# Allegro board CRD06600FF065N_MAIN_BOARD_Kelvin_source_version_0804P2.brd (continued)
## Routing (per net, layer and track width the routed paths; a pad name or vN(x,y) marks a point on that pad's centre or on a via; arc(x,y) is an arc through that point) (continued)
N17288650: length 5.7
  BOTTOM w0.508: R68.1 C36.1 R250.2 83.19,110.62 83.82,111.25 U5.2
N17289174: length 15.3
  ART05 w0.508: v1(82.55,111.12) 80.97,112.7 77.78,112.7 v1(76.2,111.12)
  BOTTOM w0.508: U5.8 v1(76.2,111.12) 76.2,110.98 76.83,110.35 C39.1 C40.1 74.17,109.98 R575.2 ; U5.3 v1(82.55,111.12)
N17289191: length 3.2
  BOTTOM w0.508: R69.1 79.38,110.91 80.01,111.54 U5.5
N17289200: length 3.2
  BOTTOM w0.508: U5.6 78.74,111.76 78.11,111.12 R70.1
N17289613: length 7.2
  BOTTOM w0.508: U5.16 85.09,120.02 84.45,120.65 R576.1 83.08,121.56 C33.1 82.55,121.54 C497.1
N17289747: length 10.1
  BOTTOM w0.508: R577.1 77.83,115.93 78.74,116.84 U5.11 78.74,119.91 78.36,120.29 C38.1
N17291315: length 4.4
  BOTTOM w0.508: C46.1 117.1,122.81 R581.1 115.47,122.77 U106.5
N17329322: length 5.4
  BOTTOM w0.381: U30.5 209.83,37.79 209.58,38.03 209.58,40.11 210.44,40.97 C245.1
N17329326: length 2.7
  BOTTOM w0.381: C245.2 208.66,40.83 208.9,40.59 208.9,39.95 208.63,39.68 U30.3
N17381506: length 2.3
  BOTTOM w0.762: R216.1 151.26,117.47 R27.2
N17381622: length 2.3
  BOTTOM w0.508: R218.1 125.35,116.85 R52.2
N17381677: length 2.3
  BOTTOM w0.508: R219.1 108.33,117.47 R51.2
N17454032: length 7.9
  BOTTOM w0.508: R186.1 174.12,13.97 C184.1 172.73,13.84 C183.1 171.57,13.97 U21.1
N17461429: length 12.6
  TOP w0.508: R244.1 C281.1 R245.2 96.57,138.43 97.84,137.16 U34.2 99.94,137.16 102.48,134.62 U34.5
N17461431: length 5.8
  TOP w0.508: R243.1 C278.2 R240.1 96.32,137.16 97.59,135.89 U34.3
N17461459: length 6.9
  TOP w0.508: U34.6 v1(102.87,135.89)
  BOTTOM w0.508: R242.1 R241.2 C280.1 103.41,134.62 102.87,135.16 v1(102.87,135.89)
N17461635: length 6.5
  TOP w0.508: R596.2 106.43,138.43 U34.8 103.38,138.43 v1(103.12,138.68)
  BOTTOM w0.508: C279.1 103.38,138.43 v1(103.12,138.68) 103.12,138.81 102.36,139.58 R239.2
N17461650: length 10.4
  TOP w0.508: U34.1 99.95,138.43 v1(100.2,138.68) 101.09,137.79 102.49,137.79 103.12,137.16 U34.7
  BOTTOM w0.508: Q60.1 100.65,138.24 v1(100.2,138.68) 100.2,139.06 R239.1 C282.2
N17461720: length 9.4
  TOP w0.508: v1(107.57,140.46) 105.14,140.46 104.5,139.83 103.12,139.83 v1(101.98,138.68)
  BOTTOM w0.508: v1(101.98,138.68) 102.55,138.12 Q60.2 ; U35.3 109.03,140.46 v1(107.57,140.46)
N17461740: length 3.8
  BOTTOM w0.508: R246.2 107.31,139.7 108.46,138.56 108.46,138.5 U35.2
N17461769: length 2.7
  BOTTOM w0.508: U35.7 118.68,137.28 R247.1
N17461771: length 5.2
  BOTTOM w0.508: R597.1 C612.1 R247.2 118.68,135.77 U35.8
N17461781: length 190.4
  ART05 w0.508: v1(120.02,140.34) 122.22,140.34 128.25,146.36 130.41,146.36 139.7,155.65 139.7,161.29 137.76,163.23 137.76,165.27 143.4,170.91 170.86,170.91 176.18,176.23 180,176.23 180.93,175.3 188.1,175.3 188.9,176.1 207.56,176.1 216.79,166.88 216.79,104.39 v1(216.53,104.14)
  BOTTOM w0.508: U35.6 v1(120.02,140.34) ; R248.2 v1(216.53,104.14)
N17577735: length 3.4
  BOTTOM w0.508: U55.1 199.87,174.98 R538.1 199.39,174.5 R539.2
N17746491: length 6.9
  BOTTOM w0.508: R578.2 165.99,112.14 C531.1 165.61,112.14 164.59,113.16 C530.1 162.71,113.54 162.2,114.05 U104.1
N17747250: length 6
  BOTTOM w0.508: U104.2 160.93,113.51 161.8,112.65 R71.2 160.14,111.88 C43.1 R72.1
N17749975: length 7.5
  BOTTOM w0.508: U106.1 119.28,114.05 119.79,113.54 C48.1 122.05,112.65 122.56,112.14 C47.1 125.09,112.14 R579.2
N17750019: length 6
  BOTTOM w0.508: U106.2 118.01,113.51 118.87,112.65 R74.2 117.22,111.88 C44.1 R73.1
N17751858: length 5.9
  BOTTOM w0.508: C41.1 160.03,122.81 R580.1 158.39,122.77 U104.5 156.92,120.19 C498.1
N17785545: length 4.1
  BOTTOM w0.508: R584.2 C533.1 C532.1 113.92,37.62 U108.1
N17785579: length 5
  BOTTOM w0.508: C544.1 R550.1 R551.2 112.65,37.43 U108.2
N17785699: length 11.9
  BOTTOM w0.381: R585.2 125.49,32.39 127.38,34.29 C541.1 C540.1 130.56,36.07 132.49,38 U107.1
N17785727: length 11.3
  BOTTOM w0.381: U107.2 131.22,38.1 130.33,37.21 125.47,37.21 R549.2 R548.1 C543.1
N17785767: length 13.2
  ART03 w0.508: v1(105.28,39.88) 107.57,39.88 110.11,42.42 v1(110.11,43.43)
  BOTTOM w0.508: v1(105.28,39.88) C542.1 105.27,41.16 R591.1 106.05,43.05 106.17,42.93 C536.1 ; U108.5 v1(110.11,43.43)
N17785926: length 15.7
  ART03 w0.508: v1(121.9,39.5) 121.9,40.87 124.33,43.31 v1(128.62,43.31)
  BOTTOM w0.381: C545.1 121.9,42.4 R590.1 v1(121.9,39.5)
  BOTTOM w0.508: C549.1 128.23,42.93 v1(128.62,43.31) 128.68,43.37 U107.5
N17788175: length 7.3
  BOTTOM w0.508: R586.2 158.24,35.69 C551.1 C550.1 155.19,36.2 154.76,36.63 U110.1
N17788213: length 6.2
  BOTTOM w0.508: R555.2 150.03,37.13 R554.1 151.49,37.14 C558.1 151.56,37.21 152.15,37.21 153.49,38.56 U110.2
N17788281: length 5.6
  BOTTOM w0.508: U109.1 173.38,39.21 C554.1 C555.1 R587.2
N17788301: length 6.1
  BOTTOM w0.508: U109.2 172.1,37.23 171.87,37 R553.2 R552.1 C557.1
N17788345: length 13.4
  ART03 w0.508: v1(145.03,40.64) 146.69,40.64 149.48,43.43 v1(150.95,43.43)
  BOTTOM w0.381: v1(145.03,40.64) 145.62,40.64 C556.1
  BOTTOM w0.508: C556.1 146.11,41.16 R589.1 146.89,43.05 147.01,42.93 C553.1 ; U110.5 v1(150.95,43.43)
N17788478: length 14.9
  ART03 w0.508: v1(162.79,39.5) 163.93,40.64 166.84,40.64 v1(169.5,43.31)
  BOTTOM w0.381: C559.1 162.79,42.4 R588.1 v1(162.79,39.5)
  BOTTOM w0.508: U109.5 169.56,43.37 v1(169.5,43.31) 169.12,42.93 C563.1
N17790300: length 4.1
  BOTTOM w0.508: R598.2 C565.1 C564.1 28.57,37.62 U112.1
N17790352: length 5
  BOTTOM w0.508: C572.1 R558.1 R559.2 27.3,37.43 U112.2
N17790406: length 4.8
  BOTTOM w0.381: U111.1 49.72,37.99 49.59,37.87 C568.1 C569.1 R599.2
N17790440: length 5.6
  BOTTOM w0.381: U111.2 48.45,37.26 R557.2 48.05,36.86 R556.1 46.44,36.94 C571.1
N17790484: length 13.1
  ART05 w0.508: v1(24.76,43.43) 21.08,43.43 v1(18.8,41.15)
  BOTTOM w0.508: U112.5 v1(24.76,43.43) ; C567.1 20.83,42.93 20.7,43.05 R592.1 19.92,41.16 C570.1 v1(18.8,41.15)
N17790617: length 14.7
  ART03 w0.508: v1(45.85,43.31) 43.69,41.15 40.78,41.15 v1(39.13,39.5)
  BOTTOM w0.508: C577.1 v1(45.85,43.31) 45.91,43.37 U111.5 ; v1(39.13,39.5) R593.1 39.13,42.4 C573.1
N17792648: length 4.1
  BOTTOM w0.508: U114.1 69.47,37.62 C578.1 C579.1 R600.2
N17792696: length 5
  BOTTOM w0.508: U114.2 68.2,37.43 R562.2 R563.1 C586.1
N17792742: length 4.8
  BOTTOM w0.381: R601.2 C583.1 C582.1 90.49,37.87 90.62,37.99 U113.1
N17792776: length 5.6
  BOTTOM w0.381: C585.1 87.34,36.94 R560.1 88.95,36.86 R561.2 89.35,37.26 U113.2
N17792812: length 13.1
  ART03 w0.508: v1(59.69,41.15) 61.98,43.43 v1(65.66,43.43)
  BOTTOM w0.508: U114.5 v1(65.66,43.43) ; v1(59.69,41.15) C584.1 60.82,41.16 R594.1 61.59,43.05 61.72,42.93 C581.1
N17792937: length 14.7
  ART03 w0.508: v1(80.03,39.5) 81.56,41.02 84.46,41.02 v1(86.75,43.31)
  BOTTOM w0.508: U113.5 86.81,43.37 v1(86.75,43.31) C591.1 ; C587.1 80.03,42.4 R595.1 v1(80.03,39.5)
N17799215: length 2.2
  BOTTOM w0.762: R565.1 159.01,50.67 D58.1
N17799359: length 4.1
  BOTTOM w0.762: D60.1 179.57,39.12 177.54,41.16 R567.1
N17812200: length 9.8
  BOTTOM w0.381: CT12.1 91.44,73.07 D61.3
N17812202: length 6
  BOTTOM w0.381: CT11.1 86.36,68.44 D62.3
N17820985: length 2.5
  BOTTOM w0.508: R569.1 53.08,7.49 R571.2
N17820987: length 2.5
  BOTTOM w0.508: R570.1 56.01,5.34 R569.2
N17880901: length 2.3
  BOTTOM w0.762: D57.1 118.24,50.67 R564.2
N17880973: length 3.2
  BOTTOM w0.762: R566.2 138.18,46.23 138.8,45.6 D59.1
N17943029: length 2.3
  BOTTOM w0.508: R28.2 168.28,116.85 R217.1
N165538091: length 9.9
  TOP w1.016: 139.62,141.57 RV2.2 ; RV2.2 142.93,141.57 ; RV2.2 141.28,143.22 ; RV1.1 142.29,149.17 ; RV1.1 140.64,147.52 ; RV1.1 138.99,149.17

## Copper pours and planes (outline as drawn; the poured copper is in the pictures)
+5V_A on TOP (solid shape): 90.5,141.46 90.5,139.6 91.25,138.85 94.64,138.85 94.9,138.59 94.9,136.93 94.65,136.69 91.77,136.69 91.17,137.29 94.49,137.29 94.49,138.3 93.6,138.3 93.6,137.29 91.17,137.29 90.33,138.13 85.06,138.13 81.55,134.62 80.72,134.62 80.56,134.78 80.56,136.13 80.64,136.22 81.28,136.22 82.26,137.2 82.26,137.79 83.57,137.79 83.57,138.43 82.8,138.43 82.8,137.79 82.26,137.79 82.26,138.48 83.26,139.49 83.26,141.39 83.57,141.7 90.26,141.7
-3V_PSW1 on BOTTOM (solid shape): 211.38,72.62 211.38,70.46 210.83,69.91 200.52,69.91 200.15,70.28 200.15,70.99 204.34,70.99 204.34,71.63 203.71,71.63 203.71,70.99 200.15,70.99 200.15,72.31 200.33,72.49 203,72.49 203.4,72.09 205.36,72.09 206.25,72.97 211.02,72.97
-3V_PSW2 on BOTTOM (solid shape): 203.48,93.17 203.48,88.89 203.02,88.42 192.33,88.42 192.02,88.73 192.02,90.68 200.15,90.68 200.15,91.31 199.39,91.31 199.39,90.68 192.02,90.68 192.02,91.06 192.33,91.36 198.4,91.36 198.5,91.47 198.5,91.49 198.78,91.77 200.3,91.77 200.63,92.1 200.63,93.24 200.94,93.55 203.1,93.55
-3V_PSW3 on BOTTOM (solid shape): 68.07,142.7 68.07,141.1 67.69,140.72 67.69,140.72 67.61,140.64 67.61,139.4 67.36,139.15 66.76,139.15 66.04,138.43 66.03,138.43 65.96,138.35 65.96,133.52 65.79,133.35 63.37,133.35 63.12,133.6 63.12,139.7 67.18,139.7 67.18,140.46 66.42,140.46 66.42,139.7 63.12,139.7 63.12,142.66 63.42,142.96 67.81,142.96
-3V_PSW4 on BOTTOM (solid shape): 170.41,24.41 172.52,24.41 172.85,24.08 172.85,22.99 172.97,22.86 173.28,22.86 173.36,22.78 175.16,22.78 176.07,21.88 177.13,21.88 177.29,21.72 177.29,20.19 177.14,20.04 168.4,20.04 168.12,20.32 168.12,23.24 172.09,23.24 172.09,24 171.32,24 171.32,23.24 168.12,23.24 168.12,24.43 168.5,24.82 170,24.82
-3V_PSW5 on BOTTOM (solid shape): 134.06,26.6 138.7,26.6 139.04,26.26 139.04,24.11 138.61,23.68 129.22,23.68 128.92,23.98 128.92,25.91 133.35,25.91 133.35,26.54 132.72,26.54 132.72,25.91 128.92,25.91 128.92,26.72 129.23,27.02 133.65,27.02
-3V_PSW7 on BOTTOM (solid shape): 149.57,25.73 151.32,25.73 151.33,25.72 152.13,25.72 152.54,25.31 153.89,25.31 153.91,25.33 155.29,25.33 155.29,25.33 155.78,24.84 155.78,24.24 156.2,23.82 157.71,23.82 157.9,23.62 157.9,22.89 157.68,22.67 147.73,22.67 147.34,23.06 147.34,25.89 147.8,26.35 148.94,26.35
-3V_PSW9 on BOTTOM (solid shape): 86.94,13.69 91.99,13.69 92.41,13.27 94.07,13.27 94.25,13.09 94.25,10.7 93.9,10.35 85.16,10.35 84.78,10.73 84.78,12.45 88.27,12.45 88.27,13.21 87.63,13.21 87.63,12.45 84.78,12.45 84.78,13.7 85.27,14.19 86.43,14.19
-3V_PSW10 on BOTTOM (solid shape): 111.07,13.69 116.12,13.69 116.54,13.27 118.83,13.27 119.09,13 119.09,10.45 118.99,10.35 109.17,10.35 108.91,10.61 108.91,12.45 113.03,12.45 113.03,13.21 112.39,13.21 112.39,12.45 108.91,12.45 108.91,13.84 109.26,14.19 110.56,14.19
-3V_PSW11 on BOTTOM (solid shape): 99,13.69 104.06,13.69 104.48,13.27 106.12,13.27 106.28,13.12 106.28,10.58 106.04,10.35 97.14,10.35 96.87,10.61 96.87,12.57 100.97,12.57 100.97,13.21 100.33,13.21 100.33,12.57 96.87,12.57 96.87,13.88 97.18,14.19 98.5,14.19
AGND on TOP (solid shape): 207.89,22.7 207.89,15.69 206.99,14.79 187.96,14.79 187.96,14.8 186.25,14.8 185.87,14.42 185.26,14.42 184.91,14.76 182.46,14.76 182.24,14.99 185.42,14.99 185.42,15.49 184.91,15.49 184.91,14.99 182.24,14.99 182.15,15.08 182.15,23.25 182.7,23.8 206.79,23.8
AGND on BOTTOM (solid shape): 132.4,167.03 132.4,162.06 132.2,161.86 130.81,161.86 130.68,162 130.68,167.22 130.81,167.35 132.08,167.35
AGND on BOTTOM (solid shape): 177.02,18.35 177.02,16.72 177.53,16.21 177.53,15.66 177.19,15.33 175.94,15.33 175.35,15.92 172.77,15.92 172.39,15.54 168.74,15.54 168.47,15.81 168.47,16 172.09,16 172.09,16.76 171.45,16.76 171.45,16 168.47,16 168.47,17.99 169.06,18.59 176.79,18.59
AGND on BOTTOM (solid shape): 60.19,142.77 60.19,135.22 59.66,134.69 56.29,134.69 56.07,134.91 54.91,134.91 54.79,135.03 54.79,135.78 54.97,135.97 56.13,135.97 57.2,137.03 57.2,138.81 57.46,139.08 57.46,139.7 58.67,139.7 58.67,140.34 57.91,140.34 57.91,139.7 57.46,139.7 57.46,140.28 58.39,141.2 58.42,141.2 58.42,142.74 58.55,142.87 60.08,142.87
AGND on BOTTOM (solid shape): 212.68,39.5 212.68,32.83 212.51,32.66 208.26,32.66 205.74,35.18 204.01,35.18 203.63,35.56 203.63,37.01 203.75,37.13 205.15,37.13 205.17,37.14 206.95,37.14 207.39,36.7 207.39,34.99 207.77,34.61 211.58,34.61 211.89,34.92 211.89,38.28 211.35,38.82 210.21,38.82 210.07,38.95 210.07,39.95 210.23,40.11 212.07,40.11
AGND on BOTTOM (solid shape): 206.29,87.48 206.29,85.36 206.66,84.99 206.66,83.99 206.46,83.78 200.13,83.78 199.81,84.11 197.6,84.11 197.26,84.45 206.12,84.45 206.12,85.09 205.49,85.09 205.49,84.45 197.26,84.45 197.21,84.5 194.71,84.5 194.54,84.66 194.54,84.71 199.39,84.71 199.39,85.34 198.75,85.34 198.75,84.71 194.54,84.71 194.54,86.87 194.75,87.08 203.47,87.08 204.23,87.84 205.93,87.84
AGND on BOTTOM (solid shape): 208.81,66.84 208.81,63.82 209.25,63.38 209.25,62.39 208.99,62.12 207.49,62.12 207.15,62.47 207.15,62.87 208.66,62.87 208.66,63.5 208.15,63.5 208.15,62.87 207.15,62.87 207.15,63.39 206.94,63.6 204.81,63.6 204.39,63.18 200.44,63.18 200.01,63.61 200.01,63.63 203.84,63.63 203.84,64.52 203.07,64.52 203.07,63.63 200.01,63.63 200.01,66.86 200.32,67.18 208.46,67.18
AGND on BOTTOM (solid shape): 155.5,20.1 155.5,17.98 155.91,17.58 155.91,16.67 155.76,16.51 153.96,16.51 153.77,16.7 153.77,17.14 155.32,17.14 155.32,17.65 154.69,17.65 154.69,17.14 153.77,17.14 153.77,17.61 153.54,17.84 151.37,17.84 150.96,17.43 149.78,17.43 149.78,17.43 149.29,17.43 148.81,16.95 147.91,16.95 147.55,17.32 147.55,18.03 150.5,18.03 150.5,18.67 149.73,18.67 149.73,18.03 147.55,18.03 147.55,19.96 147.87,20.28 155.33,20.28
AGND on BOTTOM (solid shape): 137.09,20.73 137.09,18.62 137.5,18.21 137.5,17.3 137.34,17.15 135.55,17.15 135.36,17.34 135.36,17.78 137.03,17.78 137.03,18.41 136.27,18.41 136.27,17.78 135.36,17.78 135.36,18.25 135.13,18.47 132.95,18.47 132.55,18.07 131.02,18.07 130.53,17.57 129.36,17.57 128.87,18.07 128.87,18.54 132.08,18.54 132.08,19.3 131.32,19.3 131.32,18.54 128.87,18.54 128.87,19.54 128.87,19.55 128.87,20.45 129.33,20.91 136.91,20.91
AGND on BOTTOM (solid shape): 100.2,108.64 113.16,108.64 114.25,109.73 117.09,109.73 117.7,109.12 118.44,109.12 118.87,108.91 119.3,109.12 120.3,109.12 122.65,106.77 122.65,105.37 122.74,104.02 123.98,103.46 137.46,103.46 140.34,100.59 140.34,95.25 150.43,85.16 165.17,85.16 168.28,88.27 168.28,99.06 163.83,103.5 163.83,109.09 164.47,109.73 167.89,109.73 168.28,109.35 168.28,108.6 169.11,107.77 170.8,107.77 171.49,108.46 178.41,108.46 180.63,106.23 180.63,82.84 179.71,81.92 144.78,81.92 131.62,95.07 118.68,95.07 118.67,95.08 111.41,95.08 101.87,104.63 75.18,104.63 74.56,105.24 74.56,107.33 74.87,107.64 82.21,107.64 82.43,107.42 82.43,106.69 82.7,106.43 85.03,106.43 85.3,106.7 85.3,107.4 85.49,107.58 87.85,107.58 88.61,108.34 88.61,111.02 89.27,111.68 97.16,111.68
AGND on ART02 (solid shape): outline of 6160 points within 100.21,0.75 219.07,178.93
AGND on ART03 (solid shape): outline of 1627 points within 163.86,63.35 219,111.76
AGND on GND04 (solid shape): outline of 4314 points within 99.28,2.36 208.2,45.38
AGND on ART05 (solid shape): 201.26,17.53 201.26,16.21 197.82,12.76 182.53,12.76 181.84,13.46 181.84,16.36 183.41,17.93 200.86,17.93
AGND on ART05 (solid shape): 131.23,166.95 131.23,165.11 130.78,164.67 84.84,164.67 84.79,164.62 84.79,164.61 82.15,161.98 79.99,161.98 74.35,156.35 74.35,149.06 71.77,146.48 68.27,146.48 60.67,138.88 59.12,138.88 58.7,139.3 58.7,140.34 61.43,141.52 59.21,143.5 59.21,144 65.75,150.54 69.65,150.54 71.73,152.62 71.73,160.16 75.66,164.1 81.36,164.1 83.58,166.32 125.8,166.32 126.69,167.22 130.96,167.22
AGND on ART05 (solid shape): outline of 2842 points within 75.05,24.23 218.94,113.54
AGND_N on TOP (solid shape): 81.84,141.74 81.84,139.31 81.61,139.09 81.61,137.89 81.63,137.87 81.63,137.24 81.02,136.64 80.18,136.64 79.76,136.21 79.76,134.87 80.39,134.24 80.39,130.94 80.14,130.68 78.61,130.68 78.36,130.94 78.36,134.11 78.99,134.75 78.99,136.3 78.47,136.82 78.47,137.79 81.15,137.79 81.15,138.43 80.39,138.43 80.39,137.79 79.63,137.79 79.63,138.43 78.87,138.43 78.87,137.79 78.47,137.79 78.47,139.2 78.19,139.48 78.19,141.63 78.49,141.92 81.65,141.92
AGND_N on BOTTOM (solid shape): 70.87,142.62 70.87,140.84 71.37,140.34 71.37,138.56 70.99,138.18 70.99,133.77 70.58,133.36 67.75,133.36 67.44,133.67 67.44,135.47 67.66,135.69 67.66,138.52 68.33,139.19 68.33,139.7 70.99,139.7 70.99,140.34 70.23,140.34 70.23,139.7 69.47,139.7 69.47,140.34 68.71,140.34 68.71,139.7 68.33,139.7 68.33,140.37 68.96,141 68.96,142.62 69.22,142.88 70.61,142.88
AGND_N on BOTTOM (solid shape): 97.92,136.78 97.92,133.06 97.64,132.79 87.27,132.79 86.3,131.82 86.3,126.02 86.44,125.89 86.56,125.89 86.57,125.9 87.37,125.9 88.88,124.38 90.26,124.38 90.48,124.16 90.48,122.2 90.25,121.97 89.73,121.97 88.84,121.07 88.84,120.26 88.66,120.08 87.92,120.08 87.56,119.72 86.78,119.72 86.66,119.84 86.66,120.54 87.2,121.07 87.2,123.83 86.82,124.21 85.57,124.21 84,125.78 83.1,125.78 82.8,125.48 81.08,125.48 77.09,129.46 77.09,136.91 77.34,137.16 97.54,137.16
AGND_N on ART03 (solid shape): outline of 2088 points within 33.43,118.02 109.6,146.54
P6.5V on TOP (solid shape): 186.27,13.4 188.86,13.4 188.96,13.51 190.96,13.51 191.14,13.33 191.14,10.67 190.83,10.35 180.62,10.35 179.46,9.18 160.57,9.18 159.86,8.47 159.86,6.87 160.52,6.21 161.98,6.21 162.55,5.64 162.55,4.16 161.87,3.48 159.11,3.48 158.19,4.4 158.19,10.9 158.96,11.67 178.46,11.67 179.36,12.57 185.42,12.57 185.42,13.21 184.91,13.21 184.91,12.57 179.36,12.57 180.17,13.39 184.69,13.39 184.7,13.38 185.09,13.77 185.9,13.77
PGND on TOP (solid shape): 141.34,136.97 141.34,133.73 141.1,133.49 141.1,133.48 135.51,133.48 134.41,132.38 134.41,126.32 134.31,126.22 132.64,126.22 132.51,126.35 132.51,132.29 132.51,132.3 132.51,135.8 134.34,137.63 140.68,137.63
PGND on TOP (solid shape): outline of 2552 points within 149.78,32.38 215.9,169.34
PGND on BOTTOM (solid shape): 31.04,133.47 31.04,126.94 33.45,124.53 54.93,124.53 61.25,130.84 62.8,130.84 63.24,130.41 63.24,125.46 64.19,124.51 67.41,124.51 67.64,124.28 67.64,121.23 67.13,120.72 64.73,120.72 63.76,119.76 62.72,119.76 62.72,119.7 61.45,118.43 61.45,114.11 61.07,113.73 14.51,113.73 13.32,114.92 13.32,120.27 63.37,120.27 63.37,120.9 62.87,120.9 62.87,120.27 13.32,120.27 13.32,122.56 67.18,122.56 67.18,123.7 66.42,123.7 66.42,122.56 13.32,122.56 13.32,133.72 14.67,135.08 29.43,135.08
PGND on BOTTOM (solid shape): outline of 1033 points within 132.49,53.64 214.04,168.19
PGND on GND04 (solid shape): outline of 11896 points within 24.13,28.42 219.16,169.64
PGND on ART05 (solid shape): outline of 2011 points within 109.35,105.94 213.52,167.51
SGND on TOP (solid shape): 123.44,5.46 123.44,1.52 123.19,1.27 122.17,1.27 121.79,1.65 121.79,5.46 121.92,5.59 123.32,5.59
SGND on TOP (solid shape): outline of 372 points within 212.09,12.06 218.19,22.23
SGND on BOTTOM (solid shape): 124.93,14.75 124.93,11.8 124.09,10.95 124.09,9.63 125.53,8.19 125.53,1.49 124.95,0.91 121.52,0.91 121.15,1.28 121.15,4.99 121.43,5.26 123.69,5.26 123.96,5.53 123.96,8.64 123.29,9.31 123.29,10.83 122.65,11.47 122.65,14.81 122.79,14.95 124.73,14.95
SGND on BOTTOM (solid shape): 92.64,7.4 92.64,5.28 93.05,4.88 93.05,3.97 92.89,3.81 91.1,3.81 90.91,4 90.91,4.45 92.58,4.45 92.58,4.95 91.95,4.95 91.95,4.45 90.91,4.45 90.91,4.91 90.68,5.14 88.5,5.14 88.1,4.73 85.14,4.73 84.84,5.04 84.84,5.21 87.63,5.21 87.63,5.97 87,5.97 87,5.21 84.84,5.21 84.84,7.32 85.09,7.58 92.46,7.58
SGND on BOTTOM (solid shape): 104.7,7.4 104.7,5.28 105.11,4.88 105.11,3.97 104.96,3.81 103.16,3.81 102.97,4 102.97,4.45 104.52,4.45 104.52,5.08 104.01,5.08 104.01,4.45 102.97,4.45 102.97,4.91 102.74,5.14 100.57,5.14 100.16,4.73 96.7,4.73 96.48,4.95 96.48,5.21 99.69,5.21 99.69,5.97 99.06,5.97 99.06,5.21 96.48,5.21 96.48,7.37 96.68,7.58 104.53,7.58
SGND on BOTTOM (solid shape): 116.77,7.4 116.77,5.28 117.18,4.88 117.18,3.97 117.02,3.81 115.23,3.81 115.04,4 115.04,4.45 116.71,4.45 116.71,4.95 116.08,4.95 116.08,4.45 115.04,4.45 115.04,4.91 114.81,5.14 112.63,5.14 112.23,4.73 108.76,4.73 108.55,4.95 108.55,5.33 111.76,5.33 111.76,5.84 111.12,5.84 111.12,5.33 108.55,5.33 108.55,7.37 108.75,7.58 116.59,7.58
SGND on ART02 (solid shape): outline of 1165 points within 84.35,0.8 124.92,21.8
SGND on ART03 (solid shape): outline of 345 points within 83.93,24.89 91.75,38.99
SGND on GND04 (solid shape): outline of 6954 points within 14.58,0.54 219.18,40.79
SGND on ART05 (solid shape): outline of 977 points within 83.69,1.85 135.56,8.37
AC_L on BOTTOM (solid shape): outline of 154 points within 121.13,140.58 134.62,158.75
AC_L on ART02 (solid shape): outline of 971 points within 41.84,126.21 135.2,167.68
AC_L on ART03 (solid shape): outline of 1286 points within 110.97,101.22 158.43,159.11
AC_L on GND04 (solid shape): outline of 1878 points within 40.91,126.96 135.26,159.38
AC_L_SAMP on TOP (solid shape): 108.82,176.69 124.84,176.69 125.73,175.8 125.73,167 124.43,165.71 89.99,165.71 88.9,166.8 88.9,175.01 89.87,175.98 99.34,175.98 101.51,178.15 107.35,178.15
AC_L_SAMP on BOTTOM (solid shape): 124.21,178.44 124.21,171.7 122.81,170.31 89.53,170.31 88.9,170.94 88.9,178.69 89.53,179.32 123.32,179.32
AC_L_SAMP on ART03 (solid shape): outline of 123 points within 88.9,147.53 134.14,178.15
AC_L_SAMP on GND04 (solid shape): outline of 430 points within 88.9,147.8 140.02,178.15
AC_L_SAMP on ART05 (solid shape): 108.82,176.69 124.84,176.69 125.73,175.8 125.73,168.66 124.59,167.51 89.71,167.51 88.9,168.33 88.9,175.01 89.87,175.98 99.34,175.98 101.51,178.15 107.35,178.15
ACL1 on TOP (solid shape): 79.38,177.42 79.38,171.29 73.82,165.74 56.94,165.74 56.43,166.24 56.43,177.7 56.98,178.24 78.55,178.24
ACL1 on BOTTOM (solid shape): 71.1,176.89 78.71,176.89 79.38,176.23 79.38,171.52 76,168.14 76,168.11 75.92,168.03 57.06,168.03 56.43,168.66 56.43,176.21 57.12,176.89 64.5,176.89 65.97,178.37 69.63,178.37
ACL1 on ART03 (solid shape): 79.38,177.73 79.38,171.38 73.35,165.35 57.07,165.35 56.43,165.99 56.43,177.76 56.98,178.3 78.8,178.3
ACL1 on GND04 (solid shape): 79.38,177.92 79.38,171.54 73.18,165.35 57.07,165.35 56.43,165.99 56.43,177.56 57.26,178.38 78.92,178.38
ACL1 on ART05 (solid shape): 79.38,177.42 79.38,175.17 79.4,175.14 79.4,171.31 73.82,165.74 56.94,165.74 56.43,166.24 56.43,177.7 56.98,178.24 78.55,178.24
ACN1 on TOP (solid shape): 79.38,157.48 79.38,148.29 78.81,147.72 57.21,147.72 56.48,148.46 56.48,157.57 56.77,157.86 78.99,157.86
ACN1 on BOTTOM (solid shape): 79.38,157.48 79.38,148.38 78.77,147.77 57.11,147.77 56.49,148.39 56.49,157.59 56.77,157.86 78.99,157.86
ACN1 on ART03 (solid shape): 79.38,159.11 79.38,148.52 78.63,147.77 56.87,147.77 56.48,148.17 56.48,159.15 57.17,159.84 78.65,159.84
ACN1 on GND04 (solid shape): 79.38,159.11 79.38,146.86 78.78,146.26 57.12,146.26 56.48,146.91 56.48,159.15 57.17,159.84 78.65,159.84
CLAMPQ8 on TOP (solid shape): 28.45,51.56 28.45,44.32 28.19,44.07 26.54,44.07 26.42,44.2 26.42,51.69 26.67,51.94 28.07,51.94
CLAMPQ9 on TOP (solid shape): 69.34,51.56 69.34,44.32 69.09,44.07 67.44,44.07 67.31,44.2 67.31,51.69 67.56,51.94 68.96,51.94
CLAMPQ10 on TOP (solid shape): 113.79,51.56 113.79,44.32 113.54,44.07 111.89,44.07 111.76,44.2 111.76,51.69 112.01,51.94 113.41,51.94
CLAMPQ11 on TOP (solid shape): 154.64,51.56 154.64,44.32 154.38,44.07 152.73,44.07 152.6,44.2 152.6,51.69 152.86,51.94 154.25,51.94
CLAMPQ12 on TOP (solid shape): 49.53,51.69 49.53,44.07 49.4,43.94 47.75,43.94 47.62,44.07 47.62,51.82 47.75,51.94 49.28,51.94
CLAMPQ13 on TOP (solid shape): 90.43,51.69 90.43,44.07 90.31,43.94 88.65,43.94 88.53,44.07 88.53,51.82 88.65,51.94 90.18,51.94
CLAMPQ14 on TOP (solid shape): 134.84,51.69 134.84,44.07 134.71,43.94 133.06,43.94 132.93,44.07 132.93,51.82 133.06,51.94 134.58,51.94
CLAMPQ15 on TOP (solid shape): 175.71,51.69 175.71,44.07 175.58,43.94 173.93,43.94 173.8,44.07 173.8,51.82 173.93,51.94 175.45,51.94
CLAMPQ15 on BOTTOM (solid shape): 178.31,49.53 178.31,44.7 177.93,44.32 174.62,44.32 174.37,44.58 174.37,46.86 173.86,47.37 173.86,51.56 174.12,51.82 176.02,51.82
DC_14V_INPUT on TOP (solid shape): 197.67,8.98 197.67,4.88 197.16,4.37 195.29,4.37 194.55,5.1 194.55,6.53 193.71,7.37 185.58,7.37 184.31,6.1 173.42,6.1 172.93,6.59 171.12,6.59 170.69,7.02 170.69,8.14 171.09,8.54 180.04,8.54 181.14,9.64 197.01,9.64
DRV_L_G on BOTTOM (solid shape): 177.29,28.32 177.29,25.4 177.08,25.18 176.42,25.18 175.45,24.21 173.95,24.21 173.85,24.31 173.85,24.32 173.07,25.1 171.42,25.1 170.99,25.53 172.85,25.53 172.85,26.29 172.09,26.29 172.09,25.53 170.99,25.53 170.61,25.91 168.76,25.91 168.43,26.24 168.43,27.05 172.85,27.05 172.85,27.81 172.09,27.81 172.09,27.05 168.43,27.05 168.43,27.15 168.68,27.41 170.79,27.41 171.6,28.22 173.41,28.22 173.69,28.5 177.11,28.5
DRVA_G on TOP (solid shape): 111,51.56 111,44.2 110.87,44.07 109.22,44.07 109.09,44.2 109.09,51.44 109.47,51.82 110.74,51.82
DRVA_G on BOTTOM (solid shape): 138.99,31.98 138.99,29.21 138.74,28.96 137.08,28.96 136.13,28.01 133.75,28.01 133.5,27.77 129.44,27.77 129.12,28.09 129.12,28.32 133.48,28.32 133.48,28.96 132.72,28.96 132.72,28.32 129.12,28.32 129.12,29.25 129.3,29.43 131.43,29.43 131.59,29.59 131.59,29.72 133.48,29.72 133.48,30.48 132.72,30.48 132.72,29.72 131.59,29.72 131.59,30.45 131.91,30.77 133.25,30.77 133.87,31.39 133.87,32.06 134.08,32.27 138.7,32.27
DRVC_G on TOP (solid shape): 151.84,51.56 151.84,44.2 151.71,44.07 150.06,44.07 149.94,44.2 149.94,51.44 150.32,51.82 151.59,51.82
DRVC_G on BOTTOM (solid shape): 158.07,30.1 158.07,27.92 158.07,27.91 158.07,27.25 157.87,27.05 155.44,27.05 155.12,26.73 152.19,26.73 151.82,26.36 149.95,26.36 149.32,26.99 147.86,26.99 147.85,26.99 147.66,26.99 147.39,27.26 147.39,28.93 147.67,29.2 149.59,29.2 149.95,28.85 151.71,28.85 153.25,30.39 157.78,30.39
EARTH on BOTTOM (solid shape): 18.39,158.87 18.39,154.39 17.95,153.95 7.22,153.95 6.94,154.23 6.94,158.57 7.55,159.18 18.08,159.18
EARTH on BOTTOM (solid shape): 107.44,166.88 107.44,163.19 107.19,162.94 107.18,162.94 107.07,162.83 83.42,162.83 81.5,160.91 65.91,160.91 65.9,160.92 58.78,160.92 58.52,161.19 58.52,164.44 58.92,164.85 78.93,164.85 81.47,167.39 106.93,167.39
EARTH on ART02 (solid shape): 5.97,178.69 5.97,159.64 6.48,159.13 17.91,159.13 18.29,158.75 18.29,153.8 18.8,153.29 28.32,153.29 28.57,153.54 28.57,163.58 29.72,164.72 60.07,164.72 60.8,163.99 60.8,159.24 60.18,158.62 36.45,158.62 34.8,156.97 34.8,150.88 33.53,149.61 2.67,149.61 1.02,151.26 1.02,178.82 1.52,179.32 5.33,179.32
HM1 on ART03 (solid shape): 102.89,78.62 102.89,63.17 104.67,61.4 114.86,61.4 117.05,59.21 124.21,59.21 125.48,57.94 125.48,47.5 124.84,46.86 122.56,46.86 121.92,47.5 121.92,53.33 121.03,54.22 109.71,54.22 108.53,53.03 108.53,47.33 108.29,47.1 106.85,47.1 106.57,47.38 106.57,52.93 105.28,54.22 99.12,54.22 93.95,59.39 93.95,77.66 92.07,79.55 86.58,79.55 84.87,81.25 84.87,89.1 85.99,90.22 91.28,90.22
HM1 on GND04 (solid shape): outline of 175 points within 84.87,46.86 125.35,90.22
HM1 on ART05 (solid shape): 91.44,90.17 91.44,90.07 102.88,78.62 102.88,63.2 104.68,61.4 110.67,61.4 112.72,59.35 124.71,59.35 125.35,58.71 125.35,47.12 125.09,46.86 121.92,46.86 121.54,47.24 121.54,52.91 120.78,53.68 115.91,53.68 115.5,53.68 109.61,53.68 108.53,52.6 108.53,47.41 108.21,47.09 106.82,47.09 106.55,47.36 106.55,52.72 105.28,53.99 99.77,53.99 95.54,58.22 95.54,77.27 93.38,79.43 86.5,79.43 84.87,81.05 84.87,89.1 85.99,90.22 91.39,90.22
HM2 on ART03 (solid shape): outline of 167 points within 114.93,46.86 166.12,74.3
HM3 on GND04 (solid shape): 56.52,87 56.52,78.97 56.49,78.95 56.49,78.19 51.1,72.8 51.1,64.56 40.51,53.98 40.51,47.5 40.01,46.99 36.58,46.99 36.07,47.5 36.07,53.41 35.56,53.91 24.39,53.91 23.19,52.72 23.19,47.49 22.76,47.06 21.53,47.06 21.25,47.34 21.25,56.42 21.98,57.15 24.13,57.15 26.67,59.69 33.68,59.69 38.73,64.74 38.73,86.36 40.01,87.63 55.88,87.63
HM3 on ART05 (solid shape): 56.52,87 56.52,79.12 56.51,79.12 56.51,70.1 40.39,53.98 40.39,47.24 40.13,46.99 35.81,46.99 35.43,47.37 35.43,53.24 34.67,54 26.4,54 26.4,54 24.41,54 23.18,52.77 23.18,47.32 22.9,47.04 21.43,47.04 21.21,47.25 21.21,56.21 22.15,57.15 22.16,57.15 25.53,60.53 34.54,60.53 43.23,69.21 43.23,86.33 44.54,87.63 55.88,87.63
HM4 on ART03 (solid shape): 28.32,69.01 28.32,65.54 29.82,64.04 36.09,64.04 36.2,63.94 49.82,63.94 49.92,64.04 79.25,64.04 81.03,62.26 81.03,47.37 80.64,46.99 77.22,46.99 76.58,47.62 76.58,53.31 75.69,54.2 65.38,54.2 64.08,52.9 64.08,47.36 63.8,47.07 62.35,47.07 62.09,47.34 62.09,52.59 62.08,52.59 60.48,54.19 43.81,54.19 41.26,56.74 23.32,56.74 20.53,59.53 20.53,66.48 20.47,66.55 20.47,68.71 20.5,68.74 20.53,68.74 20.56,68.77 20.56,68.79 22.18,70.41 26.92,70.41
IGND on TOP (solid shape): 192.59,6.41 192.59,2.74 192.1,2.24 171.23,2.24 170.67,2.8 170.67,5.35 171.16,5.84 172.21,5.84 172.83,5.23 185.3,5.23 187.04,6.97 192.03,6.97
IPFC on TOP (solid shape): 106.68,159 106.68,152.91 105.92,152.15 102.36,152.15 102.31,152.09 98.86,152.09 98.3,151.53 98.3,148.21 98.54,147.96 101.57,147.96 102.09,147.44 102.09,145.03 101.48,144.43 88.06,144.43 87.79,144.7 87.79,159.16 88.77,160.15 105.54,160.15
IPFC on BOTTOM (solid shape): 106.68,159 106.68,152.91 105.92,152.15 102.36,152.15 102.31,152.09 98.86,152.09 98.3,151.53 98.3,148.21 98.74,147.76 101.05,147.76 101.47,147.34 101.47,143.13 100.58,142.24 77.22,142.24 76.92,142.54 76.92,144.68 77.33,145.09 82.28,145.09 83.07,145.89 83.07,158.67 84.55,160.15 105.54,160.15
IPFC on ART03 (solid shape): 106.68,159 106.68,147.45 105.8,146.57 102.85,146.57 102.02,145.74 102.02,145.7 100.59,144.27 82.8,144.27 82.46,144.61 82.46,159.32 83.29,160.15 105.54,160.15
IPFC on GND04 (solid shape): 106.68,159 106.68,150.89 100.21,144.43 83.31,144.43 82.46,145.27 82.46,159.32 83.29,160.15 105.54,160.15
IPFC on ART05 (solid shape): 106.68,157.86 106.68,152.91 105.92,152.15 102.36,152.15 102.31,152.09 98.86,152.09 98.3,151.53 98.3,148.21 98.74,147.76 100.78,147.76 101.3,147.24 101.3,145.19 100.54,144.43 88.02,144.43 87.43,145.01 87.43,157.41 88.18,158.16 106.38,158.16
L on TOP (solid shape): 21.46,176.85 21.46,175.13 20.01,173.68 20.01,173.66 19.68,173.33 19.68,170.05 20.01,169.72 20.04,169.72 21.46,168.3 21.46,167.32 20.47,166.51 19.79,165.44 16.55,162.2 7.41,162.2 6.52,163.09 6.52,165.74 18.28,177.49 20.81,177.49
L on BOTTOM (solid shape): 21.62,176.59 21.62,175.54 19.56,173.48 19.56,172.98 19.55,172.97 19.46,172.09 19.55,171.2 19.56,171.19 19.56,170.42 19.68,170.3 19.68,170.06 20.13,169.61 20.15,169.61 21.53,168.22 21.53,167.16 16.58,162.2 7.81,162.2 6.52,163.49 6.52,165.74 18.28,177.49 18.97,177.49 19.01,177.53 20.68,177.53
L on ART03 (solid shape): 21.61,176.68 21.61,175.28 20.01,173.68 20.01,173.66 19.68,173.33 19.68,170.13 21.52,168.29 21.52,167.17 16.55,162.2 7.41,162.2 6.52,163.09 6.52,169.79 9.19,172.46 9.19,176.03 10.65,177.49 20.79,177.49
L on GND04 (solid shape): 21.66,176.59 21.66,175.32 19.68,173.33 19.68,170.17 21.47,168.38 21.47,167.12 16.55,162.2 7.41,162.2 6.52,163.09 6.52,169.79 9.19,172.46 9.19,176.03 10.65,177.49 20.76,177.49
L on ART05 (solid shape): 21.56,176.79 21.56,175.23 20.01,173.68 20.01,173.66 19.68,173.33 19.68,170.18 21.57,168.29 21.57,167.23 19.79,165.45 19.79,165.44 16.55,162.2 7.41,162.2 6.52,163.09 6.52,169.79 9.19,172.46 9.19,176.03 10.65,177.49 18.97,177.49 18.98,177.5 20.84,177.5
N on TOP (solid shape): 43.31,152.55 43.31,140.31 42.04,139.04 7.05,139.04 5.99,140.1 5.99,149.88 7.01,150.9 35.99,150.9 38.66,153.57 42.29,153.57
N on BOTTOM (solid shape): 53.13,153.22 53.13,151.34 52.66,150.88 43.81,150.88 43.31,150.37 43.31,139.93 42.42,139.04 7.01,139.04 6.12,139.93 6.12,150.02 7.01,150.9 35.99,150.9 38.66,153.57 52.78,153.57
N on ART03 (solid shape): 43.31,152.51 43.31,140.31 42.04,139.04 7.05,139.04 5.99,140.1 5.99,152.52 7.04,153.57 42.24,153.57
N on GND04 (solid shape): 43.31,153.08 43.31,140.69 41.66,139.04 7.05,139.04 5.99,140.1 5.99,152.52 7.04,153.57 42.81,153.57
N on ART05 (solid shape): 42.96,152.97 42.96,139.96 42.04,139.04 7.05,139.04 5.99,140.1 5.99,149.88 7.01,150.9 35.99,150.9 38.66,153.57 40.24,153.57 40.25,153.58 42.35,153.58
PCS+ on TOP (solid shape): 176.51,71.16 176.51,56.25 175.48,55.22 173.05,55.22 170.59,52.76 170.59,47.39 170.29,47.09 168.82,47.09 168.62,47.29 168.62,52.94 165.21,56.35 131.88,56.35 129.67,54.13 129.67,47.45 129.23,47.01 128.17,47.01 127.72,47.47 127.72,57.05 136.71,66.04 163.45,66.04 164.85,67.44 164.85,67.44 169.29,71.88 175.38,71.88 175.39,71.89 175.78,71.89
PCS+ on BOTTOM (solid shape): 175.45,71.91 176.04,71.91 176.54,71.41 176.54,56.2 175.74,55.4 173.18,55.4 170.57,52.78 170.57,47.45 170.11,47 168.93,47 168.58,47.35 168.58,53.07 166.09,55.55 138.23,55.55 136.78,54.1 130.86,54.1 129.72,52.96 129.72,47.43 129.38,47.09 127.93,47.09 127.72,47.3 127.72,57.56 142.07,71.91 175.45,71.91
PFC_G_A on BOTTOM (solid shape): 198.48,96.22 202.97,96.22 203.24,95.95 203.24,94.45 202.89,94.11 200.38,94.11 199.87,93.6 199.87,92.48 199.77,92.38 198.6,92.38 198.15,92.84 199.39,92.84 199.39,93.6 198.63,93.6 198.63,92.84 198.15,92.84 197.89,93.09 195.61,93.09 195.33,92.81 192.07,92.81 191.77,93.12 191.77,95 200.03,95 200.03,95.76 199.39,95.76 199.39,95 191.77,95 191.77,96.82 192.02,97.08 197.61,97.08
PFC_L on ART02 (solid shape): outline of 1317 points within 113.67,106.1 177.37,134.21
SPGND on TOP (solid shape): outline of 990 points within 4.45,26.52 85.27,51.98
SPGND on BOTTOM (solid shape): 54.25,57.91 54.25,55.02 54.08,54.85 54.08,54.84 53.9,54.66 48.55,54.66 47.29,54.66 45.93,54.66 44.42,53.14 44.42,47.36 44.12,47.07 42.53,47.07 42.42,47.18 42.42,54.86 45.85,58.29 53.87,58.29
SPGND on BOTTOM (solid shape): 13.8,35.53 13.8,33.96 15.66,32.1 16.19,32.1 16.2,32.11 18.84,32.11 18.84,32.11 23.16,32.11 24.71,33.66 56.79,33.66 57.52,32.93 78.25,32.93 78.27,32.91 81.73,32.91 82.43,32.21 82.43,20.84 81.28,19.68 58.84,19.68 58.2,20.32 58.2,26.02 56.66,27.57 52.03,27.57 49.12,30.48 29.21,30.48 28.57,29.84 25.36,29.84 23.44,27.93 23.44,25.98 23.12,25.67 12.67,25.67 12.25,26.1 12.25,28.09 9.46,30.88 2.45,30.88 1.7,31.64 1.7,37.27 2.59,38.16 11.16,38.16
SPGND on ART02 (solid shape): outline of 2590 points within 25.6,19.72 91.4,52.47
SPGND on ART05 (solid shape): outline of 785 points within 0.92,0.72 76.89,40.94
SR_L_G on BOTTOM (solid shape): 119.17,17.98 119.17,15.06 118.77,14.65 116.57,14.65 116.24,14.98 113.85,14.98 113.18,14.31 111.56,14.31 111.01,14.86 113.03,14.86 113.03,15.49 112.39,15.49 112.39,14.86 111.01,14.86 110.9,14.96 109.17,14.96 108.92,15.21 108.92,16.38 113.03,16.38 113.03,17.02 112.39,17.02 112.39,16.38 108.92,16.38 108.92,16.39 109.17,16.63 111.15,16.63 112.01,17.5 113.12,17.5 113.93,18.31 118.84,18.31
SRA_G on TOP (solid shape): 25.65,51.56 25.65,44.2 25.53,44.07 23.88,44.07 23.75,44.2 23.75,51.44 24.13,51.82 25.4,51.82
SRA_G on BOTTOM (solid shape): 94.18,18.14 94.18,15.06 93.77,14.65 92.44,14.65 92.11,14.98 89.72,14.98 89.05,14.31 87.43,14.31 86.88,14.86 88.9,14.86 88.9,15.49 88.27,15.49 88.27,14.86 86.88,14.86 86.77,14.96 86.75,14.96 86.64,15.08 85.08,15.08 84.76,15.39 84.76,16.38 88.9,16.38 88.9,17.02 88.27,17.02 88.27,16.38 84.76,16.38 84.76,16.39 85.03,16.65 87.03,16.65 87.88,17.5 88.99,17.5 89.8,18.31 94.01,18.31
SRC_G on TOP (solid shape): 66.55,51.56 66.55,44.2 66.42,44.07 64.77,44.07 64.64,44.2 64.64,51.44 65.02,51.82 66.29,51.82
SRC_G on BOTTOM (solid shape): 106.2,18.08 106.2,14.87 105.99,14.65 104.5,14.65 104.18,14.98 101.79,14.98 101.12,14.31 99.49,14.31 98.94,14.86 100.97,14.86 100.97,15.49 100.33,15.49 100.33,14.86 98.94,14.86 98.83,14.96 97.26,14.96 96.89,15.33 96.89,16.26 100.97,16.26 100.97,16.89 100.33,16.89 100.33,16.26 96.89,16.26 96.89,16.43 97.14,16.67 99.12,16.67 99.95,17.5 101.06,17.5 101.91,18.36 105.92,18.36
VDCLOW+15V on BOTTOM (solid shape): 177.29,31.55 177.29,29.97 177.11,29.79 173.66,29.79 173.61,29.84 173.1,29.84 172.72,29.46 172.72,29.11 172.52,28.91 171.2,28.91 170.74,28.45 168.76,28.45 168.28,28.93 168.28,29.34 172.09,29.34 172.09,30.1 171.32,30.1 171.32,29.34 168.28,29.34 168.28,31.45 168.76,31.93 176.91,31.93
VLOW+15V on BOTTOM (solid shape): 211.58,78.94 211.58,74.68 211.28,74.37 206.15,74.37 205.77,74.75 205.77,75.74 205.66,75.84 200.38,75.84 200.03,76.2 200.03,76.33 204.34,76.33 204.34,76.96 203.84,76.96 203.84,76.33 200.03,76.33 200.03,78.49 200.71,79.17 211.35,79.17
VO+ on TOP (solid shape): 79.68,6.56 79.68,2.07 79.17,1.57 54.87,1.57 53.98,3.86 53.08,1.57 12.05,1.57 10.96,2.65 10.96,4.94 13.43,7.41 78.83,7.41
VO+ on BOTTOM (solid shape): 59.82,58.05 59.82,47.5 59.31,46.99 56.64,46.99 56.26,47.37 56.26,54.1 57.4,55.24 57.4,58.17 57.54,58.31 59.56,58.31
VO+ on BOTTOM (solid shape): 82.2,7.92 82.2,2.35 81.28,1.44 60.66,1.44 60.07,2.03 60.02,2.03 60.02,7.88 60.83,8.68 81.44,8.68
VO+ on ART02 (solid shape): 78.99,6.48 78.99,2.16 78.49,1.65 54.95,1.65 53.98,3.86 53,1.65 12.19,1.65 11.43,2.41 11.43,5.08 13.84,7.49 77.98,7.49
VO+ on ART03 (solid shape): outline of 2862 points within 10.39,0.86 82.92,52.44
VP+5V on TOP (solid shape): 207.99,13.19 207.99,10.91 207.51,10.43 194.68,10.43 194.46,10.65 194.46,13.2 194.76,13.5 207.68,13.5
VP+5V on BOTTOM (solid shape): 207.39,39.06 209.01,39.06 209.09,38.99 209.09,38.55 208.99,38.45 207.42,38.45 206.93,37.96 203.83,37.96 203.69,38.1 203.69,39.82 203.91,40.04 206.41,40.04
VP+15V on BOTTOM (solid shape): 213.69,65.99 213.69,59.66 213.46,59.44 210.44,59.44 210.19,59.69 210.19,61.75 209.85,62.08 209.85,62.87 211.07,62.87 211.07,63.5 210.44,63.5 210.44,62.87 209.85,62.87 209.85,63.5 210.29,63.93 210.29,65.94 210.72,66.37 213.31,66.37
VP+15V on BOTTOM (solid shape): 213.11,85.6 214.63,85.6 215.01,85.22 215.01,83.82 214.38,83.19 212.08,83.19 210.44,81.55 207.96,81.55 207.52,81.99 207.52,83.69 207.39,83.82 207.39,84.45 208.53,84.45 208.53,85.09 207.9,85.09 207.9,84.45 207.39,84.45 207.39,85.09 207.77,85.47 207.77,87.48 208.16,87.87 210.83,87.87
VP+15V on BOTTOM (solid shape): 166.93,18.11 166.93,11.74 167.63,11.04 177.56,11.04 178.25,11.72 178.25,13.05 179.7,13.05 179.7,13.83 178.88,13.83 178.88,13.05 178.25,13.05 178.25,15.19 178.17,15.27 179.25,15.27 179.25,15.86 178.66,15.86 178.66,15.27 178.17,15.27 178.11,15.33 178.11,16.46 178.45,16.8 178.45,19.24 178.79,19.58 180.22,19.58 180.5,19.3 180.5,10.89 179.23,9.62 168.03,9.62 167.3,8.88 167.3,7.3 166.91,6.91 165.85,6.91 165.37,7.39 165.37,8.34 163.79,9.92 157.57,9.92 156.74,10.75 156.74,14.23 158.11,14.23 158.11,15.14 157.22,15.14 157.22,14.23 156.74,14.23 156.74,15.91 156.52,16.13 156.52,16.25 157.88,16.25 157.88,17.16 156.99,17.16 156.99,16.25 156.52,16.25 156.52,16.53 156.52,16.53 156.52,17.63 156.85,17.96 158.59,17.96 158.59,18.87 157.7,18.87 157.7,17.96 156.85,17.96 156.92,18.02 156.92,19.4 157.18,19.66 165.38,19.66
VP+15V_DCDCA on BOTTOM (solid shape): 138.82,35.05 138.82,34 138.55,33.73 133.96,33.73 133.3,33.07 133.3,31.67 133.05,31.42 131.59,31.42 130.58,30.41 129.56,30.41 129.29,30.68 129.29,31.45 129.84,32 132.72,32 132.72,32.77 131.95,32.77 131.95,32 129.84,32 133.01,35.18 138.69,35.18
VP+15V_DCDCB on BOTTOM (solid shape): 157.61,33.15 157.61,31.96 157.48,31.83 153.35,31.83 151.88,30.37 151.88,29.84 151.55,29.51 150.38,29.51 150.11,29.77 147.62,29.77 147.39,30 147.39,31.13 147.72,31.46 151.77,31.46 153.59,33.27 157.48,33.27
VP+15V_HF_PFC on BOTTOM (solid shape): 202.44,98.17 202.44,97.34 201.93,96.84 198.76,96.84 198.53,97.07 198.53,97.28 200.03,97.28 200.03,98.04 199.39,98.04 199.39,97.28 198.53,97.28 198.53,98.09 198.15,98.47 191.78,98.47 191.55,98.7 191.54,98.7 191.54,99.62 191.77,99.85 200.76,99.85
VP-5V on BOTTOM (solid shape): 209.08,37.87 209.08,37.33 209.33,37.07 211.2,37.07 211.46,36.82 211.46,35.5 211.2,35.24 207.96,35.24 207.77,35.43 207.77,37.91 207.9,38.04 208.91,38.04
VPFC on TOP (solid shape): 154.05,142.32 154.15,142.24 154.08,142.13 154.94,137.24 155.8,142.13 155.73,142.24 155.83,142.32 172.46,142.32 172.56,142.24 172.5,142.13 173.35,137.24 174.21,142.13 174.15,142.24 174.25,142.32 190.88,142.32 191.52,137.37 192.15,142.32 194.4,142.32 195.16,141.56 195.16,134.54 194.52,133.9 184.32,133.9 183.64,133.22 183.64,126.75 182.88,125.98 180.47,125.98 179.71,126.75 179.71,133.99 179.2,134.49 161.29,134.49 160.27,133.48 160.27,126.24 159.89,125.86 156.72,125.86 156.46,126.11 156.46,132.97 156.21,133.22 155.83,133.22 155.82,133.21 144.7,133.21 144.43,133.48 144.43,137.57 149.18,142.32
VPFC on BOTTOM (solid shape): 187.48,51.92 187.48,49.94 185.37,47.82 185.37,46.2 184.35,45.19 182.93,45.19 182.68,45.44 182.68,51.15 183.76,52.23 187.18,52.23
VPFC on BOTTOM (solid shape): 208.39,151.25 208.39,124.46 208.4,124.45 208.4,111.85 207.82,111.28 206.25,111.28 205.49,112.04 205.49,114.68 206.76,115.95 206.76,128.91 205.49,130.18 205.49,150.91 206.25,151.67 207.96,151.67
VPFC on BOTTOM (solid shape): outline of 312 points within 151.09,125.48 194.01,142.64
VPFC on ART02 (solid shape): outline of 7534 points within 49.65,31.53 208.63,169.04
VPFC on ART03 (solid shape): outline of 2680 points within 148.23,107.41 211.69,178.18
VPFC_LF+15V on TOP (solid shape): 76.77,142.1 76.77,139.15 77.75,138.17 77.75,136.91 78.17,136.49 78.17,134.66 77.84,134.33 72.01,134.33 71.64,134.7 71.64,137.16 77.34,137.16 77.34,137.67 76.71,137.67 76.71,137.16 71.64,137.16 71.64,142.09 72.16,142.61 76.26,142.61
VPFC_LF+15V on BOTTOM (solid shape): 73.91,141.4 73.91,133.47 73.79,133.34 72.56,133.34 72.39,133.5 72.39,138.95 72.07,139.28 72.07,139.83 73.28,139.83 73.28,140.34 72.77,140.34 72.77,139.83 72.07,139.83 72.07,140.58 71.68,140.97 71.68,142.35 71.97,142.64 72.67,142.64
VS+5V on BOTTOM (solid shape): 128.39,10.94 128.39,4.32 128.4,4.32 129.29,3.43 129.29,1.52 129.16,1.4 127,1.4 126.98,1.42 126.98,8.86 126.65,9.18 125.18,9.18 124.84,9.53 124.84,10.92 125.08,11.16 128.17,11.16
VS+15V on TOP (solid shape): 123.32,8.89 123.32,6.6 123.06,6.35 121.79,6.35 121.67,6.48 121.67,8.89 121.92,9.14 123.06,9.14
VS+15V on BOTTOM (solid shape): 107.96,7.36 107.96,1.26 107.74,1.05 106.2,1.05 105.94,1.31 105.94,3.62 105.72,3.83 105.72,5.1 106.12,5.5 106.12,7.25 106.34,7.48 107.84,7.48
VS+15V on BOTTOM (solid shape): 95.89,7.36 95.89,1.26 95.68,1.05 94.13,1.05 93.87,1.31 93.87,3.62 93.66,3.83 93.66,4.45 94.87,4.45 94.87,5.08 94.23,5.08 94.23,4.45 93.66,4.45 93.66,5.1 94.05,5.5 94.05,7.25 94.28,7.48 95.78,7.48
VS+15V on BOTTOM (solid shape): 122.53,10.95 122.53,9.28 123.17,8.64 123.17,6.86 122.98,6.67 120.33,6.67 120.08,6.41 120.08,1.55 119.86,1.34 118.32,1.34 118.06,1.6 118.06,3.88 118.89,3.88 118.89,4.42 118.29,4.42 118.29,3.88 118.06,3.88 118.06,3.91 117.84,4.12 117.84,5.06 118.24,5.45 118.24,7.24 118.47,7.48 118.48,7.48 119.13,8.13 120.27,8.13 121.16,9.02 121.16,10.89 121.35,11.08 122.4,11.08
VS+15V on ART03 (solid shape): outline of 258 points within 93.6,0.73 120.14,6.32
VS+15V_DCDCA on BOTTOM (solid shape): 94.16,21.14 94.16,20.05 93.84,19.73 89.41,19.73 88.85,19.18 88.85,18.34 88.6,18.08 87.14,18.08 86.72,17.66 85.03,17.66 84.78,17.91 84.78,18.54 88.27,18.54 88.27,19.3 87.63,19.3 87.63,18.54 84.78,18.54 84.78,20.86 85.29,21.38 93.92,21.38
VS+15V_DCDCB on BOTTOM (solid shape): 106.18,20.92 106.18,20.03 105.91,19.76 101.32,19.76 100.91,19.36 100.91,18.34 100.66,18.08 99.21,18.08 98.79,17.67 97.17,17.67 96.87,17.96 96.87,18.67 100.33,18.67 100.33,19.3 99.69,19.3 99.69,18.67 96.87,18.67 96.87,20.85 97.35,21.33 105.77,21.33
VSLOW+15V on BOTTOM (solid shape): 119.08,20.89 119.08,20.06 118.79,19.77 113.4,19.77 112.98,19.35 112.98,18.34 112.73,18.08 111.27,18.08 110.85,17.67 109.31,17.67 109.02,17.96 109.02,18.67 112.39,18.67 112.39,19.3 111.76,19.3 111.76,18.67 109.02,18.67 109.02,20.86 109.37,21.21 118.75,21.21
N15409465 on TOP (solid shape): 43.94,176.4 43.94,157.96 42.93,156.94 37.56,156.94 35.56,154.94 23.37,154.94 22.1,156.21 22.1,164.15 24,166.05 24,166.15 24.17,166.33 24.17,169.43 23.49,170.12 23.47,170.12 22.22,171.37 22.22,172.28 22.55,172.61 22.55,172.63 24,174.08 24,174.68 26.52,177.2 43.14,177.2
N15409465 on BOTTOM (solid shape): 43.81,176.36 43.81,168.78 44.7,167.89 52.98,167.89 53.36,167.51 53.36,165.66 52.82,165.13 41.48,165.13 36.96,160.6 36.96,156.34 35.56,154.94 23,154.94 21.69,156.25 21.69,157.67 22.1,158.08 22.1,164.34 24.22,166.46 24.22,169.35 22.01,171.56 22.01,172.7 26.56,177.25 42.93,177.25
N15409465 on ART03 (solid shape): 43.81,176.53 43.81,155.7 43.05,154.94 23.37,154.94 23.36,154.95 22.97,154.95 21.68,156.24 21.68,157.79 22.1,158.2 22.1,164.35 23.5,165.75 23.59,165.75 24.17,166.33 24.17,169.43 23.49,170.12 23.47,170.12 22.07,171.51 22.07,172.76 26.52,177.2 43.14,177.2
N15409465 on GND04 (solid shape): 43.94,176.4 43.94,155.83 43.05,154.94 23.05,154.94 21.71,156.28 21.71,157.33 22.01,157.64 22.01,164.17 24.17,166.33 24.17,169.43 22.02,171.58 22.02,172.71 26.52,177.2 43.14,177.2
N15409465 on ART05 (solid shape): 43.94,176.4 43.94,157.96 42.93,156.94 37.56,156.94 35.56,154.94 22.84,154.94 21.68,156.1 21.68,157.77 22.1,158.19 22.1,158.2 22.1,162.5 22.09,162.51 22.09,164.41 24.17,166.49 24.17,169.43 22.07,171.54 22.07,172.76 26.52,177.2 43.14,177.2
N15414859 on BOTTOM (solid shape): 138.2,161.07 138.2,156.98 137.56,156.33 134.87,156.33 131.55,159.65 129.05,159.65 128.88,159.83 128.88,160.81 128.99,160.93 135.79,160.93 136.52,161.66 137.62,161.66
N15414880 on BOTTOM (solid shape): 138.18,170.85 138.18,169.93 136.31,168.05 131.6,168.05 130.62,169.04 128.36,169.04 128.04,169.36 128.04,171.28 128.32,171.57 137.46,171.57
N15816850 on BOTTOM (solid shape): 53.54,158.47 53.54,155.48 53.1,155.04 47.4,155.04 47.04,155.4 47.04,158.42 47.35,158.72 53.29,158.72
N15816858 on BOTTOM (solid shape): 53.5,163.56 53.5,160.28 53.35,160.12 47.4,160.12 47.04,160.48 47.04,163.5 47.35,163.8 53.26,163.8
N16123691 on TOP (solid shape): 15.62,19.16 15.62,11.55 10.95,6.87 9.96,6.87 7.48,9.35 7.48,19.36 7.99,19.87 14.92,19.87
N16123691 on BOTTOM (solid shape): 23.44,22.14 23.44,17.45 22.93,16.94 14.45,16.94 12.37,14.87 12.37,8.16 11.17,6.96 10.17,6.96 7.77,9.36 1.44,15.68 1.44,22.07 2.08,22.7 22.87,22.7
N16123691 on ART03 (solid shape): 15.62,19.16 15.62,11.55 10.95,6.87 9.96,6.87 7.48,9.35 7.48,19.36 7.99,19.87 14.92,19.87
N16123691 on GND04 (solid shape): 15.62,19.16 15.62,11.55 10.95,6.87 9.96,6.87 7.48,9.35 7.48,19.36 7.99,19.87 14.92,19.87
N16148380 on TOP (solid shape): 48.1,24.8 48.1,12.88 46.67,11.46 27.47,11.46 25.9,13.02 25.9,24.63 26.79,25.52 47.38,25.52
N16599678 on BOTTOM (solid shape): 97.84,129.98 97.84,123.87 97.4,123.43 94.96,123.43 94.67,123.14 94.67,120.24 94.42,120 93.56,120 93.4,120.16 93.4,121.51 93.01,121.9 91.53,121.9 91.18,122.25 91.18,124.14 91.43,124.39 93.18,124.39 94.74,125.96 94.74,129.91 95.12,130.28 97.54,130.28
N16600162 on BOTTOM (solid shape): 74.22,130.12 74.22,123.75 73.69,123.22 72.24,123.22 71.68,122.66 71.68,120.36 71.24,119.91 68.93,119.91 68.37,120.47 68.37,124.38 68.5,124.51 69.67,124.51 69.68,124.52 70.3,124.52 71.55,125.78 71.55,130.38 71.88,130.71 73.63,130.71
N16674941 on TOP (solid shape): 132.17,51.82 132.17,44.07 132.04,43.94 130.52,43.94 130.27,44.2 130.27,51.82 130.39,51.94 132.04,51.94
N16677707 on TOP (solid shape): 173.04,51.82 173.04,44.07 172.91,43.94 171.39,43.94 171.14,44.2 171.14,51.82 171.26,51.94 172.91,51.94
N17243036 on BOTTOM (solid shape): 135.51,167.21 135.51,161.87 135.28,161.65 133.35,161.65 133.12,161.87 133.12,162.56 134.11,162.56 134.11,163.19 133.48,163.19 133.48,162.56 133.12,162.56 133.12,163.83 135,163.83 135,164.47 134.37,164.47 134.37,163.83 134.24,163.83 134.24,164.47 133.6,164.47 133.6,163.83 133.12,163.83 133.12,165.61 134.11,165.61 134.11,166.62 133.6,166.62 133.6,165.61 133.12,165.61 133.12,167.17 133.3,167.35 135.37,167.35
N17264035 on TOP (solid shape): 46.86,51.82 46.86,44.07 46.74,43.94 45.21,43.94 44.96,44.2 44.96,51.82 45.09,51.94 46.74,51.94
N17264090 on TOP (solid shape): 87.77,51.82 87.77,44.07 87.64,43.94 86.11,43.94 85.86,44.2 85.86,51.82 85.99,51.94 87.64,51.94
N17277038 on TOP (solid shape): outline of 151 points within 11.62,58.67 36.7,87.25
N17277038 on BOTTOM (solid shape): outline of 153 points within 11.62,58.98 36.7,87.55
N17277038 on ART02 (solid shape): outline of 131 points within 11.68,58.98 36.7,87.55
N17277038 on GND04 (solid shape): outline of 133 points within 11.68,58.67 36.7,87.25
N17277038 on ART05 (solid shape): outline of 131 points within 11.68,62.22 36.7,87.55
N17452823 on BOTTOM (solid shape): 205.33,74.88 205.33,72.87 205.16,72.69 203.5,72.69 203.28,72.92 200.33,72.92 200.1,73.15 200.1,73.28 204.47,73.28 204.47,74.55 203.84,74.55 203.84,73.28 200.1,73.28 200.1,74.96 200.36,75.21 205,75.21
N17452839 on BOTTOM (solid shape): 204.83,62.18 206.47,62.18 206.48,62.2 206.53,62.2 207,61.72 208.81,61.72 209.02,61.51 209.02,59.57 208.75,59.31 200.37,59.31 200.04,59.63 200.04,61.34 203.84,61.34 203.84,61.98 203.07,61.98 203.07,61.34 200.04,61.34 200.04,62.15 200.47,62.59 204.42,62.59
N17452887 on BOTTOM (solid shape): 57.91,142.6 57.91,141.49 56.8,140.38 56.8,139.3 56.56,139.05 55.92,139.05 55.79,138.92 55.79,137.08 55.35,136.64 54.48,136.64 54.17,136.33 54.17,135.28 54.04,135.15 52.2,135.15 52,135.36 52,139.7 56.39,139.7 56.39,140.46 55.5,140.46 55.5,139.7 52,139.7 52,142.36 52.59,142.95 57.56,142.95
N17453218 on BOTTOM (solid shape): 199.79,83.34 206.17,83.34 206.47,83.04 206.47,80.53 206.19,80.25 195.06,80.25 194.86,80.45 194.86,82.42 199.39,82.42 199.39,83.06 198.75,83.06 198.75,82.42 194.86,82.42 194.86,82.83 195.21,83.19 197.6,83.19 197.9,83.49 199.64,83.49
N17453412 on BOTTOM (solid shape): 100.71,3.74 102.37,3.74 102.72,3.39 104.67,3.39 104.91,3.15 104.91,1.54 104.65,1.28 96.83,1.28 96.6,1.5 96.6,3.05 99.69,3.05 99.69,3.68 99.06,3.68 99.06,3.05 96.6,3.05 96.6,3.88 96.86,4.15 100.31,4.15
N17453587 on BOTTOM (solid shape): 88.65,3.74 90.31,3.74 90.66,3.39 92.6,3.39 92.84,3.15 92.84,1.54 92.58,1.28 85.11,1.28 84.81,1.57 84.81,3.05 87.63,3.05 87.63,3.68 87,3.68 87,3.05 84.81,3.05 84.81,3.92 85.04,4.15 88.24,4.15
N17453815 on BOTTOM (solid shape): 112.78,3.74 114.44,3.74 114.79,3.39 116.73,3.39 116.97,3.15 116.97,1.54 116.71,1.28 108.89,1.28 108.66,1.5 108.66,2.92 111.76,2.92 111.76,3.68 111.12,3.68 111.12,2.92 108.66,2.92 108.66,3.88 108.93,4.15 112.37,4.15
N17454032 on BOTTOM (solid shape): 173.11,14.52 177.02,14.52 177.22,14.32 177.22,12.84 176.94,12.56 168.7,12.56 168.4,12.86 168.4,14.67 168.66,14.93 172.71,14.93
